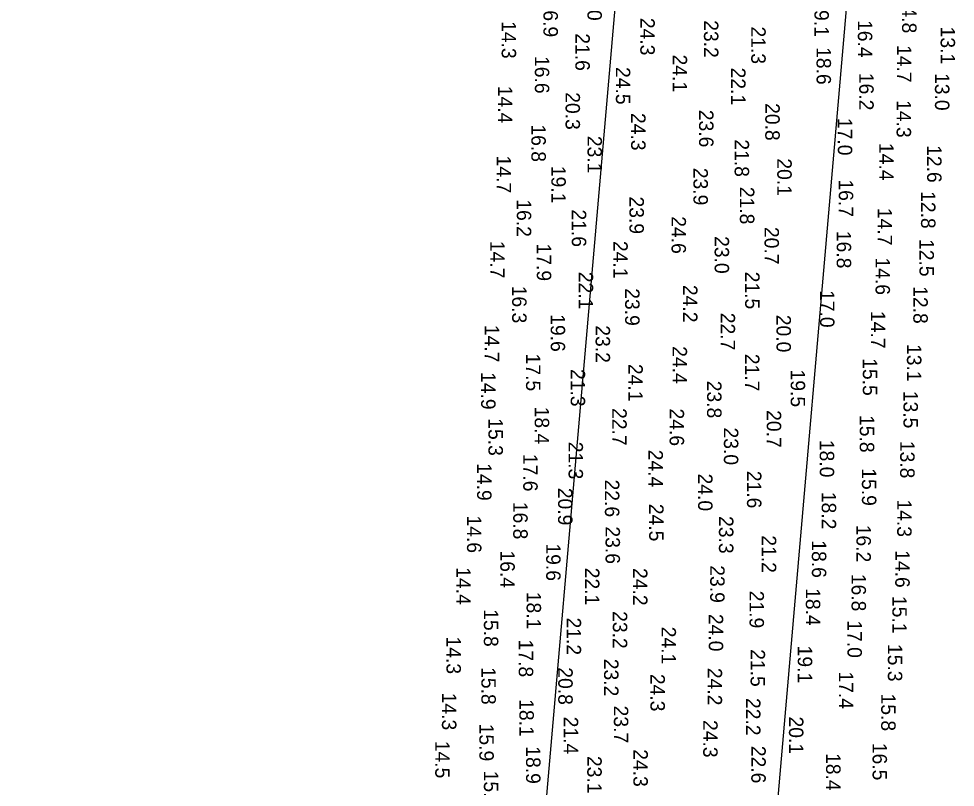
# Model space of a CAD drawing. Extents: x 1178573 to 1187098, y 693282 to 751751.
# Drawn here: x 1181662 to 1182473, y 723129 to 723794 of the extents above; entities that cross this region are included whole.
import ezdxf

# ---------------------------------------------------------------- set-up
doc = ezdxf.new("R2010")
doc.units = 0
doc.layers.add('G-ANNO-PATT', color=7, linetype='Continuous')
doc.layers.add('V-HYDS-SOUN', color=7, linetype='Continuous')

msp = doc.modelspace()

# ---------------------------------------------------------------- linework, layer by layer
at = {"layer": 'G-ANNO-PATT'}
msp.add_line((1182284.41, 722717.14), (1182404.98, 724104.25), dxfattribs=at)
msp.add_lwpolyline([(1182192.54, 723969.84), (1182074.29, 722609.41), (1181796.18, 721896.63), (1181517.07, 721534.37), (1180724.06, 720916.39)], dxfattribs=at)

# ---------------------------------------------------------------- texts
at = {"layer": 'V-HYDS-SOUN'}
for s, p in [('23.0 ', (1182154.32, 723825.08)), ('16.9 ', (1182116.24, 723810.77)), ('19.1 ', (1182350.96, 723811.06)), ('14.8 ', (1182426.91, 723814.11)), ('14.3 ', (1182080.05, 723792.17)), ('24.3 ', (1182200.16, 723794.99)), ('23.2 ', (1182255.26, 723792.92)), ('16.4 ', (1182388.58, 723793.06)), ('21.3 ', (1182296.22, 723787.51)), ('13.1 ', (1182460.27, 723787.37)), ('21.6 ', (1182143.89, 723781.6)), ('18.6 ', (1182352.81, 723769.63)), ('14.7 ', (1182422.47, 723771.46)), ('16.6 ', (1182108.79, 723761.92)), ('24.1 ', (1182228.19, 723763.19)), ('24.5 ', (1182178.97, 723752.38)), ('22.1 ', (1182278.78, 723751.9)), ('16.2 ', (1182389.78, 723747.35)), ('13.0 ', (1182455.37, 723747.16)), ('14.4 ', (1182076.9, 723736.11)), ('20.3 ', (1182135.39, 723730.58)), ('20.8 ', (1182308.4, 723721.14)), ('14.3 ', (1182422.17, 723723.76)), ('24.3 ', (1182192.18, 723712.61)), ('23.6 ', (1182251.04, 723715.36)), ('17.0 ', (1182371.22, 723708.35)), ('16.8 ', (1182105.78, 723702.7)), ('23.1 ', (1182154.4, 723692.81)), ('21.8 ', (1182281.86, 723689.77)), ('14.4 ', (1182407.08, 723686.63)), ('12.6 ', (1182448.58, 723684.78)), ('14.7 ', (1182075.75, 723675.66)), ('20.1 ', (1182318.77, 723673.33)), ('19.1 ', (1182123.1, 723666.83)), ('23.9 ', (1182246.16, 723665.16)), ('16.7 ', (1182372.07, 723655.09)), ('21.8 ', (1182286.42, 723648.69)), ('23.9 ', (1182190.75, 723640.3)), ('12.8 ', (1182443.28, 723644.95)), ('16.2 ', (1182093.16, 723637.83)), ('14.7 ', (1182405.77, 723630.39)), ('21.6 ', (1182140.81, 723629.08)), ('24.6 ', (1182227.19, 723623.17)), ('20.7 ', (1182307.74, 723613.92)), ('23.0 ', (1182264.53, 723605.99)), ('16.8 ', (1182370.28, 723610.51)), ('14.7 ', (1182070.14, 723601.94)), ('17.9 ', (1182110.5, 723599.55)), ('24.1 ', (1182176.74, 723601.8)), ('12.5 ', (1182441.96, 723603.46)), ('14.6 ', (1182403.9, 723587.51)), ('22.1 ', (1182146.79, 723575.1)), ('21.5 ', (1182290.95, 723575.18)), ('16.3 ', (1182089.13, 723563.03)), ('23.9 ', (1182187.01, 723560.83)), ('24.2 ', (1182237.15, 723563.72)), ('17.0 ', (1182355.8, 723559.27)), ('12.8 ', (1182436.62, 723562.61)), ('14.7 ', (1182399.83, 723541.15)), ('19.6 ', (1182122.53, 723538.33)), ('22.7 ', (1182269.74, 723539.61)), ('20.0 ', (1182318.1, 723537.85)), ('14.7 ', (1182065.45, 723529.14)), ('23.2 ', (1182161.43, 723528.74)), ('24.4 ', (1182228.11, 723510.65)), ('13.1 ', (1182431.11, 723512.53)), ('17.5 ', (1182101.15, 723504.22)), ('21.7 ', (1182290.81, 723504.08)), ('15.5 ', (1182392.88, 723500.25)), ('24.1 ', (1182189.8, 723495.31)), ('14.9 ', (1182062.27, 723488.29)), ('21.3 ', (1182139.85, 723490.92)), ('19.5 ', (1182330.42, 723490.41)), ('23.8 ', (1182257.98, 723480.75)), ('13.5 ', (1182428.09, 723472.03)), ('18.4 ', (1182108.69, 723458.29)), ('22.7 ', (1182175.85, 723457.06)), ('24.6 ', (1182225.55, 723456.7)), ('20.7 ', (1182309.67, 723455.29)), ('15.3 ', (1182068.6, 723448.24)), ('15.8 ', (1182390.26, 723451.06)), ('23.0 ', (1182272.53, 723440.24)), ('21.3 ', (1182137.99, 723427.93)), ('18.0 ', (1182355.57, 723429.54)), ('13.8 ', (1182425.23, 723428.71)), ('24.4 ', (1182207.21, 723421.01)), ('17.6 ', (1182098.75, 723417.36)), ('14.9 ', (1182058.8, 723409.39)), ('21.6 ', (1182292.55, 723402.76)), ('15.9 ', (1182392.1, 723404.93)), ('22.6 ', (1182169.48, 723395.15)), ('24.0 ', (1182250.19, 723400.38)), ('20.9 ', (1182128.91, 723388.03)), ('18.2 ', (1182357.27, 723384.55)), ('16.8 ', (1182090.09, 723375.89)), ('24.5 ', (1182207.81, 723374.17)), ('14.3 ', (1182422.63, 723377.96)), ('14.6 ', (1182050.03, 723364.08)), ('23.3 ', (1182268.27, 723363.56)), ('23.6 ', (1182170.04, 723354.6)), ('16.2 ', (1182387.35, 723356.07)), ('21.2 ', (1182305.4, 723346.89)), ('19.6 ', (1182118.6, 723339.87)), ('18.6 ', (1182348.75, 723342.56)), ('16.4 ', (1182078.9, 723333.78)), ('14.6 ', (1182420.99, 723334.03)), ('14.4 ', (1182040.74, 723319.24)), ('22.1 ', (1182152.24, 723318.86)), ('24.2 ', (1182193.81, 723318.57)), ('23.9 ', (1182260.67, 723320.94)), ('16.8 ', (1182383.11, 723313.56)), ('18.1 ', (1182101.65, 723298)), ('21.9 ', (1182294.75, 723298.92)), ('18.4 ', (1182343.53, 723301.13)), ('15.1 ', (1182418.48, 723294.39)), ('15.8 ', (1182064.64, 723282.91)), ('23.2 ', (1182176.33, 723281.24)), ('21.2 ', (1182136.37, 723275.69)), ('24.0 ', (1182259.44, 723278.86)), ('17.0 ', (1182379.59, 723273.28)), ('24.1 ', (1182218.54, 723267.75)), ('14.3 ', (1182032.24, 723259.26)), ('17.8 ', (1182094.85, 723256.57)), ('21.5 ', (1182295.7, 723248.28)), ('19.1 ', (1182336.55, 723251.35)), ('15.3 ', (1182414.56, 723252.8)), ('15.8 ', (1182062.47, 723232.75)), ('20.8 ', (1182129.07, 723232.59)), ('23.2 ', (1182168.75, 723240)), ('24.2 ', (1182258.48, 723232.12)), ('24.3 ', (1182208.92, 723226.91)), ('17.4 ', (1182372.14, 723229.02)), ('14.3 ', (1182028.34, 723210.64)), ('15.8 ', (1182408.8, 723209.85)), ('18.1 ', (1182095.41, 723204.99)), ('22.2 ', (1182291.71, 723206.04)), ('23.7 ', (1182177.22, 723199.42)), ('15.9 ', (1182060.73, 723183.77)), ('21.4 ', (1182133.85, 723189.85)), ('24.3 ', (1182254.62, 723186.95)), ('20.1 ', (1182328.91, 723189.99)), ('14.5 ', (1182022.51, 723168.98)), ('18.9 ', (1182101.18, 723164.21)), ('24.3 ', (1182194.15, 723161.65)), ('22.6 ', (1182296.29, 723164.61)), ('16.5 ', (1182401.31, 723167.21)), ('23.1 ', (1182154.2, 723155.84)), ('18.4 ', (1182361.08, 723158.32)), ('15.8 ', (1182064.64, 723143.09))]:
    msp.add_text(s, height=12.5, rotation=270, dxfattribs=at).set_placement(p)

doc.saveas('drawing.dxf')
